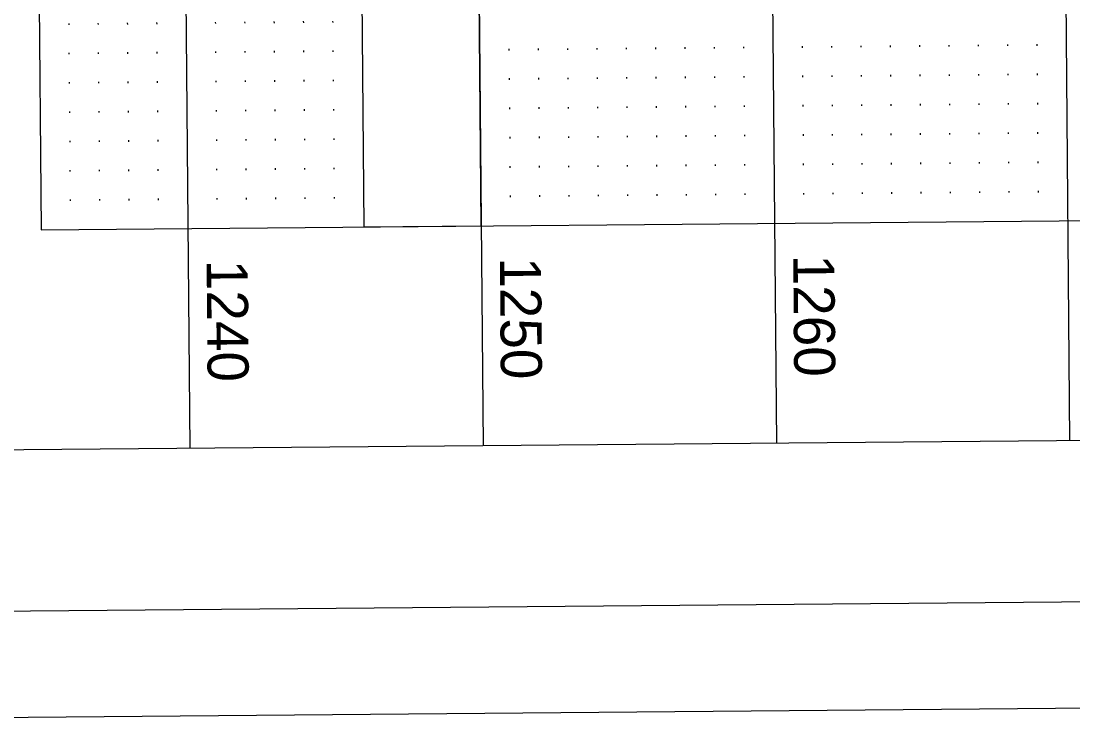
# Model space of a CAD drawing. Extents: x 2149873 to 2152007, y 140538 to 142349.
# Drawn here: x 2150010.8 to 2150190.1, y 140538.2 to 140658 of the extents above; entities that cross this region are included whole.
import ezdxf

# ---------------------------------------------------------------- set-up
doc = ezdxf.new("R2010")
doc.units = 0
for name, color, linetype in [('SHT_Plan_Profile_Sheet_Elev_Txt', 7, 'Continuous'), ('SHT_Plot_Shape_Full', 7, 'Continuous'), ('SHT_Plot_Shape_Half', 7, 'Continuous'), ('SHT_Profile_Grid_Major', 7, 'Continuous'), ('SHT_Profile_Grid_Minor', 7, 'Continuous'), ('SHT_Sheet_Border', 7, 'Continuous')]:
    doc.layers.add(name, color=color, linetype=linetype)

msp = doc.modelspace()

# ---------------------------------------------------------------- linework, layer by layer
at = {"layer": 'SHT_Plot_Shape_Full'}
msp.add_lwpolyline([(2151072.86, 142348.62), (2151088.62, 140548.69), (2149888.66, 140538.18), (2149872.91, 142338.11)], close=True, dxfattribs=at)
at = {"layer": 'SHT_Plot_Shape_Half'}
msp.add_lwpolyline([(2151032.33, 142266.38), (2151047.21, 140566.45), (2149947.25, 140556.82), (2149932.37, 142256.76)], close=True, dxfattribs=at)
at = {"layer": 'SHT_Profile_Grid_Major'}
for p, q in [((2150175.72, 142161.38), (2150189.5, 140586.44)), ((2150025.72, 142160.07), (2150039.51, 140585.13)), ((2150075.72, 142160.51), (2150089.51, 140585.57)), ((2150125.72, 142160.94), (2150139.51, 140586))]:
    msp.add_line(p, q, dxfattribs=at)
at = {"layer": 'SHT_Profile_Grid_Minor'}
for p, q in [((2150018.88, 140657.58), (2150018.88, 140657.33)), ((2150023.87, 140657.62), (2150023.88, 140657.37)), ((2150028.87, 140657.66), (2150028.88, 140657.41)), ((2150033.87, 140657.71), (2150033.88, 140657.46)), ((2150043.87, 140657.8), (2150043.88, 140657.55)), ((2150048.87, 140657.84), (2150048.88, 140657.59)), ((2150053.87, 140657.88), (2150053.88, 140657.63)), ((2150058.87, 140657.93), (2150058.88, 140657.68)), ((2150063.87, 140657.97), (2150063.88, 140657.72)), ((2150093.92, 140653.23), (2150093.92, 140652.98)), ((2150098.92, 140653.28), (2150098.92, 140653.03)), ((2150103.92, 140653.32), (2150103.92, 140653.07)), ((2150108.92, 140653.36), (2150108.92, 140653.11)), ((2150113.92, 140653.41), (2150113.92, 140653.16)), ((2150118.91, 140653.45), (2150118.92, 140653.2)), ((2150123.91, 140653.5), (2150123.92, 140653.25)), ((2150128.91, 140653.54), (2150128.92, 140653.29)), ((2150133.91, 140653.58), (2150133.92, 140653.33)), ((2150143.91, 140653.67), (2150143.92, 140653.42)), ((2150148.91, 140653.71), (2150148.92, 140653.46)), ((2150153.91, 140653.76), (2150153.92, 140653.51)), ((2150158.91, 140653.8), (2150158.92, 140653.55)), ((2150163.91, 140653.85), (2150163.92, 140653.6)), ((2150168.91, 140653.89), (2150168.92, 140653.64)), ((2150173.91, 140653.93), (2150173.92, 140653.68)), ((2150178.91, 140653.98), (2150178.91, 140653.73)), ((2150183.91, 140654.02), (2150183.91, 140653.77)), ((2150018.92, 140652.58), (2150018.92, 140652.33)), ((2150023.92, 140652.62), (2150023.92, 140652.37)), ((2150028.92, 140652.66), (2150028.92, 140652.41)), ((2150033.92, 140652.71), (2150033.92, 140652.46)), ((2150043.92, 140652.8), (2150043.92, 140652.55)), ((2150048.92, 140652.84), (2150048.92, 140652.59)), ((2150053.92, 140652.88), (2150053.92, 140652.63)), ((2150058.92, 140652.93), (2150058.92, 140652.68)), ((2150063.92, 140652.97), (2150063.92, 140652.72)), ((2150028.96, 140647.66), (2150028.96, 140647.41)), ((2150033.96, 140647.71), (2150033.96, 140647.46)), ((2150043.96, 140647.8), (2150043.96, 140647.55)), ((2150048.96, 140647.84), (2150048.96, 140647.59)), ((2150053.96, 140647.88), (2150053.96, 140647.63)), ((2150058.96, 140647.93), (2150058.96, 140647.68)), ((2150063.96, 140647.97), (2150063.96, 140647.72)), ((2150093.96, 140648.23), (2150093.96, 140647.98)), ((2150098.96, 140648.28), (2150098.96, 140648.03)), ((2150103.96, 140648.32), (2150103.96, 140648.07)), ((2150108.96, 140648.36), (2150108.96, 140648.11)), ((2150113.96, 140648.41), (2150113.96, 140648.16)), ((2150118.96, 140648.45), (2150118.96, 140648.2)), ((2150123.96, 140648.5), (2150123.96, 140648.25)), ((2150128.96, 140648.54), (2150128.96, 140648.29)), ((2150133.96, 140648.58), (2150133.96, 140648.33)), ((2150143.96, 140648.67), (2150143.96, 140648.42)), ((2150148.96, 140648.71), (2150148.96, 140648.46)), ((2150153.96, 140648.76), (2150153.96, 140648.51)), ((2150158.96, 140648.8), (2150158.96, 140648.55)), ((2150163.96, 140648.85), (2150163.96, 140648.6)), ((2150168.96, 140648.89), (2150168.96, 140648.64)), ((2150173.96, 140648.93), (2150173.96, 140648.68)), ((2150178.96, 140648.98), (2150178.96, 140648.73)), ((2150183.96, 140649.02), (2150183.96, 140648.77)), ((2150018.96, 140647.58), (2150018.96, 140647.33)), ((2150023.96, 140647.62), (2150023.96, 140647.37)), ((2150019.01, 140642.58), (2150019.01, 140642.33)), ((2150024.01, 140642.62), (2150024.01, 140642.37)), ((2150029.01, 140642.66), (2150029.01, 140642.41)), ((2150034.01, 140642.71), (2150034.01, 140642.46)), ((2150044.01, 140642.8), (2150044.01, 140642.55)), ((2150049.01, 140642.84), (2150049.01, 140642.59)), ((2150054, 140642.88), (2150054.01, 140642.63)), ((2150059, 140642.93), (2150059.01, 140642.68)), ((2150064, 140642.97), (2150064.01, 140642.72)), ((2150094, 140643.23), (2150094.01, 140642.98)), ((2150099, 140643.28), (2150099.01, 140643.03)), ((2150104, 140643.32), (2150104.01, 140643.07)), ((2150109, 140643.36), (2150109.01, 140643.11)), ((2150114, 140643.41), (2150114, 140643.16)), ((2150119, 140643.45), (2150119, 140643.2)), ((2150124, 140643.5), (2150124, 140643.25)), ((2150129, 140643.54), (2150129, 140643.29)), ((2150134, 140643.58), (2150134, 140643.33)), ((2150144, 140643.67), (2150144, 140643.42)), ((2150149, 140643.71), (2150149, 140643.46)), ((2150154, 140643.76), (2150154, 140643.51)), ((2150159, 140643.8), (2150159, 140643.55)), ((2150164, 140643.85), (2150164, 140643.6)), ((2150169, 140643.89), (2150169, 140643.64)), ((2150174, 140643.93), (2150174, 140643.68)), ((2150179, 140643.98), (2150179, 140643.73)), ((2150184, 140644.02), (2150184, 140643.77)), ((2150144.05, 140638.67), (2150144.05, 140638.42)), ((2150149.05, 140638.71), (2150149.05, 140638.46)), ((2150154.04, 140638.76), (2150154.05, 140638.51)), ((2150159.04, 140638.8), (2150159.05, 140638.55)), ((2150164.04, 140638.85), (2150164.05, 140638.6)), ((2150169.04, 140638.89), (2150169.05, 140638.64)), ((2150174.04, 140638.93), (2150174.05, 140638.68)), ((2150179.04, 140638.98), (2150179.05, 140638.73)), ((2150184.04, 140639.02), (2150184.05, 140638.77)), ((2150019.05, 140637.58), (2150019.05, 140637.33)), ((2150024.05, 140637.62), (2150024.05, 140637.37)), ((2150029.05, 140637.66), (2150029.05, 140637.41)), ((2150034.05, 140637.71), (2150034.05, 140637.46)), ((2150044.05, 140637.8), (2150044.05, 140637.55)), ((2150049.05, 140637.84), (2150049.05, 140637.59)), ((2150054.05, 140637.88), (2150054.05, 140637.63)), ((2150059.05, 140637.93), (2150059.05, 140637.68)), ((2150064.05, 140637.97), (2150064.05, 140637.72)), ((2150094.05, 140638.23), (2150094.05, 140637.98)), ((2150099.05, 140638.28), (2150099.05, 140638.03)), ((2150104.05, 140638.32), (2150104.05, 140638.07)), ((2150109.05, 140638.36), (2150109.05, 140638.11)), ((2150114.05, 140638.41), (2150114.05, 140638.16)), ((2150119.05, 140638.45), (2150119.05, 140638.2)), ((2150124.05, 140638.5), (2150124.05, 140638.25)), ((2150129.05, 140638.54), (2150129.05, 140638.29)), ((2150134.05, 140638.58), (2150134.05, 140638.33)), ((2150104.09, 140633.32), (2150104.09, 140633.07)), ((2150109.09, 140633.37), (2150109.09, 140633.12)), ((2150114.09, 140633.41), (2150114.09, 140633.16)), ((2150119.09, 140633.45), (2150119.09, 140633.2)), ((2150124.09, 140633.5), (2150124.09, 140633.25)), ((2150129.09, 140633.54), (2150129.09, 140633.29)), ((2150134.09, 140633.58), (2150134.09, 140633.33)), ((2150144.09, 140633.67), (2150144.09, 140633.42)), ((2150149.09, 140633.72), (2150149.09, 140633.47)), ((2150154.09, 140633.76), (2150154.09, 140633.51)), ((2150159.09, 140633.8), (2150159.09, 140633.55)), ((2150164.09, 140633.85), (2150164.09, 140633.6)), ((2150169.09, 140633.89), (2150169.09, 140633.64)), ((2150174.09, 140633.93), (2150174.09, 140633.68)), ((2150179.09, 140633.98), (2150179.09, 140633.73)), ((2150184.09, 140634.02), (2150184.09, 140633.77)), ((2150019.09, 140632.58), (2150019.1, 140632.33)), ((2150024.09, 140632.62), (2150024.1, 140632.37)), ((2150029.09, 140632.66), (2150029.1, 140632.41)), ((2150034.09, 140632.71), (2150034.1, 140632.46)), ((2150044.09, 140632.8), (2150044.1, 140632.55)), ((2150049.09, 140632.84), (2150049.09, 140632.59)), ((2150054.09, 140632.88), (2150054.09, 140632.63)), ((2150059.09, 140632.93), (2150059.09, 140632.68)), ((2150064.09, 140632.97), (2150064.09, 140632.72)), ((2150094.09, 140633.23), (2150094.09, 140632.98)), ((2150099.09, 140633.28), (2150099.09, 140633.03)), ((2150059.14, 140627.93), (2150059.14, 140627.68)), ((2150064.14, 140627.97), (2150064.14, 140627.72)), ((2150094.13, 140628.23), (2150094.14, 140627.98)), ((2150099.13, 140628.28), (2150099.14, 140628.03)), ((2150104.13, 140628.32), (2150104.14, 140628.07)), ((2150109.13, 140628.37), (2150109.14, 140628.12)), ((2150114.13, 140628.41), (2150114.14, 140628.16)), ((2150119.13, 140628.45), (2150119.14, 140628.2)), ((2150124.13, 140628.5), (2150124.14, 140628.25)), ((2150129.13, 140628.54), (2150129.14, 140628.29)), ((2150134.13, 140628.58), (2150134.14, 140628.33)), ((2150144.13, 140628.67), (2150144.14, 140628.42)), ((2150149.13, 140628.72), (2150149.13, 140628.47)), ((2150154.13, 140628.76), (2150154.13, 140628.51)), ((2150159.13, 140628.8), (2150159.13, 140628.55)), ((2150164.13, 140628.85), (2150164.13, 140628.6)), ((2150169.13, 140628.89), (2150169.13, 140628.64)), ((2150174.13, 140628.93), (2150174.13, 140628.68)), ((2150179.13, 140628.98), (2150179.13, 140628.73)), ((2150184.13, 140629.02), (2150184.13, 140628.77)), ((2150019.14, 140627.58), (2150019.14, 140627.33)), ((2150024.14, 140627.62), (2150024.14, 140627.37)), ((2150029.14, 140627.67), (2150029.14, 140627.42)), ((2150034.14, 140627.71), (2150034.14, 140627.46)), ((2150044.14, 140627.8), (2150044.14, 140627.55)), ((2150049.14, 140627.84), (2150049.14, 140627.59)), ((2150054.14, 140627.88), (2150054.14, 140627.63))]:
    msp.add_line(p, q, dxfattribs=at)
at = {"layer": 'SHT_Sheet_Border'}
msp.add_line((2150014.18, 140622.41), (2150489.16, 140626.57), dxfattribs=at)
for points in [[(2151008.19, 142168.67), (2151021.97, 140593.73), (2149972.01, 140584.54), (2149958.23, 142159.48)], [(2150087.87, 140773.06), (2150067.87, 140772.88), (2150069.18, 140622.89), (2150089.18, 140623.07)]]:
    msp.add_lwpolyline(points, close=True, dxfattribs=at)
msp.add_lwpolyline([(2149987.21, 140847.18), (2150012.21, 140847.4), (2150014.18, 140622.41)], dxfattribs=at)

# ---------------------------------------------------------------- texts
at = {"layer": 'SHT_Plan_Profile_Sheet_Elev_Txt'}
for s, p in [('1260', (2150142.38, 140618.14)), ('1240', (2150042.39, 140617.26)), ('1250', (2150092.38, 140617.7))]:
    msp.add_text(s, height=7, rotation=270.5015, dxfattribs=at).set_placement(p)

doc.saveas('drawing.dxf')
